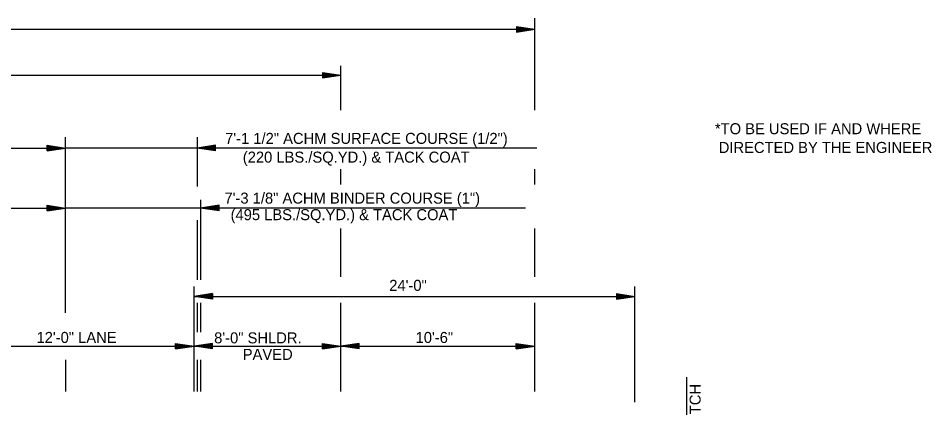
# Model space of a CAD drawing. Extents: x 1371763 to 1372860, y 385599 to 385872.
# Drawn here: x 1371855.15 to 1371904.9, y 385789.19 to 385810.39 of the extents above; entities that cross this region are included whole.
import ezdxf

# ---------------------------------------------------------------- set-up
doc = ezdxf.new("R2010")
doc.units = 0
doc.layers.add('R_Draft', color=7, linetype='Continuous')

msp = doc.modelspace()

# ---------------------------------------------------------------- linework, layer by layer
at = {"layer": 'R_Draft'}
for p, q in [((1371883.281, 385805.388), (1371883.281, 385810.386)), ((1371810.167, 385809.786), (1371883.281, 385809.786)), ((1371882.281, 385809.936), (1371883.281, 385809.786)), ((1371882.281, 385809.936), (1371882.281, 385809.636)), ((1371882.281, 385809.911), (1371883.114, 385809.786)), ((1371882.281, 385809.885), (1371882.942, 385809.786)), ((1371882.281, 385809.86), (1371882.775, 385809.786)), ((1371882.281, 385809.834), (1371882.606, 385809.786)), ((1371882.281, 385809.809), (1371882.439, 385809.786)), ((1371882.281, 385809.636), (1371883.281, 385809.786)), ((1371882.281, 385809.737), (1371882.606, 385809.786)), ((1371882.281, 385809.686), (1371882.942, 385809.786)), ((1371882.281, 385809.661), (1371883.114, 385809.786)), ((1371882.281, 385809.711), (1371882.775, 385809.786)), ((1371882.281, 385809.762), (1371882.439, 385809.786)), ((1371872.721, 385805.388), (1371872.721, 385807.796)), ((1371820.721, 385807.286), (1371872.721, 385807.286)), ((1371871.721, 385807.436), (1371872.721, 385807.286)), ((1371871.721, 385807.436), (1371871.721, 385807.136)), ((1371871.721, 385807.411), (1371872.554, 385807.286)), ((1371871.721, 385807.385), (1371872.382, 385807.286)), ((1371871.721, 385807.36), (1371872.216, 385807.286)), ((1371871.721, 385807.334), (1371872.046, 385807.286)), ((1371871.721, 385807.309), (1371871.879, 385807.286)), ((1371871.721, 385807.136), (1371872.721, 385807.286)), ((1371871.721, 385807.237), (1371872.046, 385807.286)), ((1371871.721, 385807.186), (1371872.382, 385807.286)), ((1371871.721, 385807.161), (1371872.554, 385807.286)), ((1371871.721, 385807.211), (1371872.216, 385807.286)), ((1371871.721, 385807.262), (1371871.879, 385807.286)), ((1371857.723, 385794.343), (1371857.724, 385803.919)), ((1371864.893, 385803.919), (1371864.893, 385801.236)), ((1371835.724, 385803.324), (1371857.724, 385803.324)), ((1371856.724, 385803.474), (1371857.724, 385803.324)), ((1371856.724, 385803.174), (1371856.724, 385803.474)), ((1371856.724, 385803.449), (1371857.557, 385803.324)), ((1371856.724, 385803.424), (1371857.385, 385803.324)), ((1371856.724, 385803.399), (1371857.219, 385803.324)), ((1371856.724, 385803.373), (1371857.049, 385803.324)), ((1371856.724, 385803.348), (1371856.882, 385803.324)), ((1371856.724, 385803.174), (1371857.724, 385803.324)), ((1371856.724, 385803.276), (1371857.049, 385803.324)), ((1371856.724, 385803.225), (1371857.385, 385803.324)), ((1371856.724, 385803.199), (1371857.557, 385803.324)), ((1371856.724, 385803.25), (1371857.219, 385803.324)), ((1371856.724, 385803.301), (1371856.882, 385803.324)), ((1371883.4, 385803.324), (1371857.724, 385803.324)), ((1371865.893, 385803.474), (1371864.893, 385803.324)), ((1371865.893, 385803.174), (1371864.893, 385803.324)), ((1371865.893, 385803.449), (1371865.06, 385803.324)), ((1371865.893, 385803.199), (1371865.06, 385803.324)), ((1371865.893, 385803.423), (1371865.232, 385803.324)), ((1371865.893, 385803.224), (1371865.232, 385803.324)), ((1371865.893, 385803.398), (1371865.398, 385803.324)), ((1371865.893, 385803.249), (1371865.398, 385803.324)), ((1371865.893, 385803.373), (1371865.568, 385803.324)), ((1371865.893, 385803.275), (1371865.568, 385803.324)), ((1371865.893, 385803.347), (1371865.735, 385803.324)), ((1371865.893, 385803.3), (1371865.735, 385803.324)), ((1371865.893, 385803.174), (1371865.893, 385803.474)), ((1371872.721, 385801.341), (1371872.721, 385802.169)), ((1371883.281, 385801.341), (1371883.281, 385802.169)), ((1371856.724, 385800.207), (1371857.724, 385800.057)), ((1371856.724, 385799.907), (1371856.724, 385800.207)), ((1371856.724, 385800.182), (1371857.557, 385800.057)), ((1371865.082, 385800.508), (1371865.082, 385796.148)), ((1371866.082, 385800.208), (1371865.082, 385800.058)), ((1371866.082, 385800.183), (1371865.249, 385800.058)), ((1371866.082, 385799.908), (1371866.082, 385800.208)), ((1371835.724, 385800.057), (1371857.724, 385800.057)), ((1371856.724, 385800.157), (1371857.385, 385800.057)), ((1371856.724, 385800.132), (1371857.219, 385800.057)), ((1371856.724, 385800.106), (1371857.049, 385800.057)), ((1371856.724, 385800.081), (1371856.882, 385800.057)), ((1371856.724, 385799.907), (1371857.724, 385800.057)), ((1371856.724, 385800.009), (1371857.049, 385800.057)), ((1371856.724, 385799.958), (1371857.385, 385800.057)), ((1371856.724, 385799.932), (1371857.557, 385800.057)), ((1371856.724, 385799.983), (1371857.219, 385800.057)), ((1371856.724, 385800.034), (1371856.882, 385800.057)), ((1371882.766, 385800.058), (1371857.724, 385800.058)), ((1371866.082, 385799.908), (1371865.082, 385800.058)), ((1371866.082, 385799.933), (1371865.249, 385800.058)), ((1371866.082, 385800.157), (1371865.421, 385800.058)), ((1371866.082, 385799.958), (1371865.421, 385800.058)), ((1371866.082, 385800.132), (1371865.587, 385800.058)), ((1371866.082, 385799.983), (1371865.587, 385800.058)), ((1371866.082, 385800.107), (1371865.757, 385800.058)), ((1371866.082, 385800.009), (1371865.757, 385800.058)), ((1371866.082, 385800.081), (1371865.924, 385800.058)), ((1371866.082, 385800.034), (1371865.924, 385800.058)), ((1371864.893, 385799.396), (1371864.893, 385796.148)), ((1371872.721, 385796.306), (1371872.721, 385798.943)), ((1371883.281, 385796.306), (1371883.281, 385798.943)), ((1371864.721, 385790.075), (1371864.722, 385795.788)), ((1371888.722, 385789.49), (1371888.722, 385795.788)), ((1371865.722, 385795.398), (1371864.722, 385795.248)), ((1371864.722, 385795.248), (1371888.722, 385795.248)), ((1371865.722, 385795.098), (1371864.722, 385795.248)), ((1371865.722, 385795.373), (1371864.889, 385795.248)), ((1371865.722, 385795.123), (1371864.889, 385795.248)), ((1371865.722, 385795.347), (1371865.061, 385795.248)), ((1371865.722, 385795.148), (1371865.061, 385795.248)), ((1371865.722, 385795.322), (1371865.227, 385795.248)), ((1371865.722, 385795.173), (1371865.227, 385795.248)), ((1371865.722, 385795.296), (1371865.397, 385795.248)), ((1371865.722, 385795.199), (1371865.397, 385795.248)), ((1371865.722, 385795.271), (1371865.564, 385795.248)), ((1371865.722, 385795.224), (1371865.564, 385795.248)), ((1371865.722, 385795.398), (1371865.722, 385795.098)), ((1371887.722, 385795.398), (1371888.722, 385795.248)), ((1371887.722, 385795.398), (1371887.722, 385795.098)), ((1371887.722, 385795.373), (1371888.555, 385795.248)), ((1371887.722, 385795.347), (1371888.383, 385795.248)), ((1371887.722, 385795.322), (1371888.216, 385795.248)), ((1371887.722, 385795.296), (1371888.047, 385795.248)), ((1371887.722, 385795.271), (1371887.88, 385795.248)), ((1371887.722, 385795.098), (1371888.722, 385795.248)), ((1371887.722, 385795.199), (1371888.047, 385795.248)), ((1371887.722, 385795.148), (1371888.383, 385795.248)), ((1371887.722, 385795.123), (1371888.555, 385795.248)), ((1371887.722, 385795.173), (1371888.216, 385795.248)), ((1371887.722, 385795.224), (1371887.88, 385795.248)), ((1371864.893, 385794.899), (1371864.893, 385793.291)), ((1371865.082, 385794.899), (1371865.082, 385793.291)), ((1371872.721, 385790.069), (1371872.721, 385794.897)), ((1371883.281, 385790.069), (1371883.281, 385794.896)), ((1371852.721, 385792.541), (1371864.721, 385792.541)), ((1371863.721, 385792.691), (1371864.721, 385792.541)), ((1371863.721, 385792.391), (1371863.721, 385792.691)), ((1371863.721, 385792.666), (1371864.554, 385792.541)), ((1371863.721, 385792.641), (1371864.382, 385792.541)), ((1371863.721, 385792.616), (1371864.216, 385792.541)), ((1371863.721, 385792.59), (1371864.046, 385792.541)), ((1371863.721, 385792.565), (1371863.879, 385792.541)), ((1371863.721, 385792.391), (1371864.721, 385792.541)), ((1371863.721, 385792.493), (1371864.046, 385792.541)), ((1371863.721, 385792.442), (1371864.382, 385792.541)), ((1371863.721, 385792.416), (1371864.554, 385792.541)), ((1371863.721, 385792.467), (1371864.216, 385792.541)), ((1371863.721, 385792.518), (1371863.879, 385792.541)), ((1371865.721, 385792.69), (1371864.721, 385792.54)), ((1371865.721, 385792.39), (1371864.721, 385792.54)), ((1371864.721, 385792.54), (1371872.721, 385792.54)), ((1371865.721, 385792.665), (1371864.888, 385792.54)), ((1371865.721, 385792.415), (1371864.888, 385792.54)), ((1371865.721, 385792.64), (1371865.06, 385792.54)), ((1371865.721, 385792.441), (1371865.06, 385792.54)), ((1371865.721, 385792.615), (1371865.227, 385792.54)), ((1371865.721, 385792.466), (1371865.227, 385792.54)), ((1371865.721, 385792.589), (1371865.396, 385792.54)), ((1371865.721, 385792.492), (1371865.396, 385792.54)), ((1371865.721, 385792.564), (1371865.563, 385792.54)), ((1371865.721, 385792.517), (1371865.563, 385792.54)), ((1371865.721, 385792.39), (1371865.721, 385792.69)), ((1371871.721, 385792.69), (1371872.721, 385792.54)), ((1371871.721, 385792.39), (1371871.721, 385792.69)), ((1371871.721, 385792.665), (1371872.554, 385792.54)), ((1371871.721, 385792.64), (1371872.382, 385792.54)), ((1371871.721, 385792.615), (1371872.216, 385792.54)), ((1371871.721, 385792.589), (1371872.046, 385792.54)), ((1371871.721, 385792.564), (1371871.879, 385792.54)), ((1371871.721, 385792.39), (1371872.721, 385792.54)), ((1371871.721, 385792.492), (1371872.046, 385792.54)), ((1371871.721, 385792.441), (1371872.382, 385792.54)), ((1371871.721, 385792.415), (1371872.554, 385792.54)), ((1371871.721, 385792.466), (1371872.216, 385792.54)), ((1371871.721, 385792.517), (1371871.879, 385792.54)), ((1371873.721, 385792.69), (1371872.721, 385792.54)), ((1371873.721, 385792.39), (1371872.721, 385792.54)), ((1371872.721, 385792.54), (1371883.281, 385792.54)), ((1371873.721, 385792.665), (1371872.888, 385792.54)), ((1371873.721, 385792.415), (1371872.888, 385792.54)), ((1371873.721, 385792.64), (1371873.06, 385792.54)), ((1371873.721, 385792.441), (1371873.06, 385792.54)), ((1371873.721, 385792.615), (1371873.227, 385792.54)), ((1371873.721, 385792.466), (1371873.227, 385792.54)), ((1371873.721, 385792.589), (1371873.396, 385792.54)), ((1371873.721, 385792.492), (1371873.396, 385792.54)), ((1371873.721, 385792.564), (1371873.563, 385792.54)), ((1371873.721, 385792.517), (1371873.563, 385792.54)), ((1371873.721, 385792.39), (1371873.721, 385792.69)), ((1371882.275, 385792.689), (1371883.275, 385792.539)), ((1371882.275, 385792.389), (1371882.275, 385792.689)), ((1371882.275, 385792.664), (1371883.108, 385792.539)), ((1371882.275, 385792.639), (1371882.936, 385792.539)), ((1371882.275, 385792.614), (1371882.769, 385792.539)), ((1371882.275, 385792.588), (1371882.6, 385792.539)), ((1371882.275, 385792.563), (1371882.433, 385792.539)), ((1371882.275, 385792.389), (1371883.275, 385792.539)), ((1371882.275, 385792.491), (1371882.6, 385792.539)), ((1371882.275, 385792.44), (1371882.936, 385792.539)), ((1371882.275, 385792.414), (1371883.108, 385792.539)), ((1371882.275, 385792.465), (1371882.769, 385792.539)), ((1371882.275, 385792.516), (1371882.433, 385792.539)), ((1371857.723, 385791.791), (1371857.723, 385790.075)), ((1371864.893, 385791.791), (1371864.893, 385790.075)), ((1371865.082, 385791.791), (1371865.082, 385790.075)), ((1371891.57, 385784.55), (1371891.57, 385790.848))]:
    msp.add_line(p, q, dxfattribs=at)

# ---------------------------------------------------------------- texts
for s, rotation, p in [('*TO BE USED IF AND WHERE ', 360, (1371893.09, 385804.074)), ('7\'-1 1/2" ACHM SURFACE COURSE (1/2")', 0, (1371866.416, 385803.548)), ('DIRECTED BY THE ENGINEER', 360, (1371893.3, 385803.054)), ('(220 LBS./SQ.YD.) & TACK COAT', 0, (1371867.378, 385802.528)), ('7\'-3 1/8" ACHM BINDER COURSE (1")', 0, (1371866.38, 385800.296)), ('(495 LBS./SQ.YD.) & TACK COAT', 0, (1371866.713, 385799.396)), ('12\'-0" LANE', 360, (1371856.143, 385792.713)), ('8\'-0" SHLDR.', 360, (1371865.818, 385792.69)), ('10\'-6"', 360, (1371876.789, 385792.711)), ('PAVED', 360, (1371867.375, 385791.79)), ('MIN. DITCH', 90, (1371892.314, 385786.113))]:
    msp.add_text(s, height=0.6, rotation=rotation, dxfattribs=at).set_placement(p)
msp.add_text('24\'-0"', height=0.6, dxfattribs=at).set_placement((1371875.354, 385795.548))

doc.saveas('drawing.dxf')
